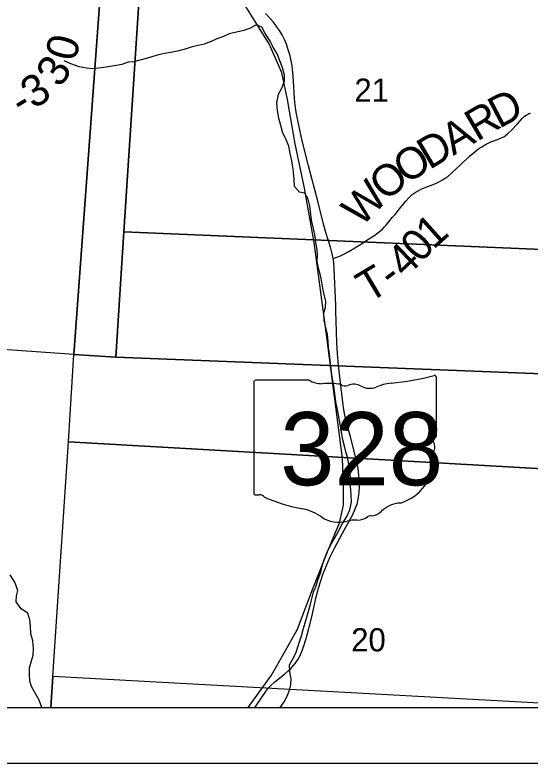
# Model space of a CAD drawing. Extents: x 0 to 34, y 0 to 22.
# Drawn here: x 5.134 to 6.063, y 14 to 15.349 of the extents above; entities that cross this region are included whole.
import ezdxf

# ---------------------------------------------------------------- set-up
doc = ezdxf.new("R2010")
doc.units = 0
for name, color, linetype in [('GM_X_Corporation', 7, 'Continuous'), ('GM_X_Minor_River', 7, 'Continuous'), ('GM_X_Rail_Line', 7, 'Continuous'), ('GM_X_Section_Text', 7, 'Continuous'), ('GM_X_State_Location', 7, 'Continuous'), ('GM_X_State_Route', 7, 'Continuous'), ('GM_X_State_Shield', 7, 'Continuous'), ('GM_X_Township_Road', 7, 'Continuous'), ('GM_X_Township_Road_Text', 7, 'Continuous'), ('SH_Data', 7, 'Continuous')]:
    doc.layers.add(name, color=color, linetype=linetype)

msp = doc.modelspace()

# ---------------------------------------------------------------- linework, layer by layer
at = {"layer": 'GM_X_Corporation'}
for points in [[(5.3151, 15.7607), (5.2401, 14.7366), (4.7622, 14.7706), (4.8134, 15.7898)], [(5.3826, 15.7568), (5.3302, 14.958), (5.3154, 14.7318), (5.2401, 14.7366), (5.3151, 15.7607)], [(6.3225, 15.705), (6.2563, 14.9189), (5.3302, 14.958), (5.3826, 15.7568)], [(6.2563, 14.9189), (6.2382, 14.6961), (5.3154, 14.7318), (5.3302, 14.958)], [(4.1967, 14.1), (5.1981, 14.1), (5.2017, 14.1562), (5.23, 14.5792), (5.2401, 14.7366), (4.7622, 14.7706), (4.245, 14.8084)], [(5.3154, 14.7318), (6.2382, 14.6961), (6.2242, 14.5225), (5.23, 14.5792), (5.2401, 14.7366)], [(5.23, 14.5792), (6.2242, 14.5225), (6.1902, 14.1019), (5.2017, 14.1562)], [(5.1981, 14.1), (6.19, 14.1), (6.1902, 14.1019), (5.2017, 14.1562)]]:
    msp.add_lwpolyline(points, close=True, dxfattribs=at)
at = {"layer": 'GM_X_Minor_River'}
for points in [[(5.667, 14.9948), (5.6657, 15.0046), (5.663, 15.0167), (5.6565, 15.0276), (5.647, 15.0294), (5.6378, 15.04), (5.6377, 15.0525), (5.6364, 15.0653), (5.6348, 15.0752), (5.6325, 15.0892), (5.6305, 15.099), (5.6277, 15.1126), (5.6223, 15.1259), (5.6173, 15.1357), (5.6134, 15.15), (5.6099, 15.1629), (5.6071, 15.1765), (5.6059, 15.1901), (5.6091, 15.2064), (5.6147, 15.216), (5.6203, 15.2297), (5.6202, 15.2407), (5.6163, 15.2535), (5.6124, 15.2652), (5.607, 15.2792), (5.5989, 15.292), (5.5939, 15.3018), (5.5851, 15.3154), (5.5789, 15.3271), (5.5694, 15.3311), (5.557, 15.3246), (5.5464, 15.3211), (5.5336, 15.3179), (5.52, 15.3152), (5.5098, 15.3105), (5.5, 15.3066), (5.4857, 15.3004), (5.4752, 15.2962), (5.4532, 15.2914), (5.4423, 15.2879), (5.4272, 15.2836), (5.4076, 15.2804), (5.3951, 15.278), (5.3826, 15.2741), (5.3728, 15.2714), (5.3589, 15.2675), (5.3479, 15.2647), (5.3381, 15.2642), (5.3264, 15.26), (5.3128, 15.2572), (5.2981, 15.2552), (5.2845, 15.2531), (5.2742, 15.2519), (5.2625, 15.2529), (5.2492, 15.2555), (5.2344, 15.261), (5.2223, 15.2666)], [(5.6123, 14.1), (5.6194, 14.1106), (5.625, 14.1205), (5.6291, 14.1312), (5.6316, 14.1414), (5.6319, 14.1516), (5.6295, 14.1645), (5.629, 14.1774), (5.6365, 14.1896), (5.6413, 14.1999), (5.6454, 14.2132), (5.6509, 14.2295), (5.6538, 14.2409), (5.6571, 14.2531), (5.6601, 14.2629), (5.6638, 14.2759), (5.6674, 14.2891), (5.67, 14.2986), (5.6725, 14.3085), (5.6763, 14.318), (5.681, 14.3317), (5.6855, 14.3443), (5.6884, 14.3572), (5.6917, 14.3667), (5.6973, 14.38), (5.7032, 14.3929), (5.7107, 14.4063), (5.7181, 14.4192), (5.7248, 14.4322), (5.7327, 14.4447), (5.7382, 14.4569), (5.7408, 14.4706), (5.7403, 14.4846), (5.7394, 14.4986), (5.7389, 14.5107), (5.7388, 14.5244), (5.7368, 14.5372), (5.7336, 14.5509), (5.7309, 14.5614), (5.7285, 14.5713), (5.725, 14.5853), (5.723, 14.5974), (5.7202, 14.6114), (5.7179, 14.6242), (5.7155, 14.6367), (5.7127, 14.6511), (5.7107, 14.6662), (5.709, 14.6802), (5.7067, 14.6923), (5.705, 14.7052), (5.7038, 14.7162), (5.7022, 14.726), (5.701, 14.7381), (5.6997, 14.7491), (5.6989, 14.7601), (5.6976, 14.773), (5.6949, 14.7855), (5.6917, 14.7976), (5.6909, 14.8116), (5.6942, 14.8218), (5.6948, 14.8328), (5.6925, 14.8427), (5.6901, 14.8525), (5.6874, 14.8672), (5.6854, 14.8771), (5.6815, 14.8922), (5.6791, 14.9047), (5.6797, 14.9157), (5.6789, 14.9259), (5.6765, 14.9384), (5.6753, 14.9497), (5.6721, 14.9641), (5.669, 14.9789), (5.667, 14.9948)], [(5.1822, 14.1), (5.1821, 14.1002), (5.1775, 14.1134), (5.1694, 14.127), (5.1632, 14.1379), (5.1605, 14.1477), (5.1596, 14.161), (5.1599, 14.1716), (5.1636, 14.1845), (5.1662, 14.1944), (5.1672, 14.2058), (5.1656, 14.2202), (5.162, 14.233), (5.1619, 14.247), (5.1603, 14.258), (5.1568, 14.2701), (5.145, 14.2783), (5.1358, 14.2908), (5.1361, 14.3018), (5.139, 14.3113), (5.1336, 14.326), (5.1252, 14.3395)]]:
    msp.add_lwpolyline(points, dxfattribs=at)
at = {"layer": 'GM_X_Rail_Line'}
msp.add_lwpolyline([(5.5547, 14.1), (5.5967, 14.1582), (5.6212, 14.2017), (5.6432, 14.2417), (5.6703, 14.3127), (5.6986, 14.3836), (5.7193, 14.433), (5.7265, 14.4652), (5.7264, 14.5008), (5.7246, 14.5493), (5.6967, 14.7678), (5.6733, 14.9386), (5.6564, 15.0367), (5.639, 15.1164), (5.6254, 15.1965), (5.6154, 15.2447), (5.593, 15.2957), (5.5443, 15.3738)], dxfattribs=at)
at = {"layer": 'GM_X_State_Route'}
msp.add_lwpolyline([(5.5667, 14.1), (5.5685, 14.1026), (5.5875, 14.131), (5.5914, 14.1359), (5.5957, 14.1405), (5.6028, 14.1466), (5.6198, 14.1602), (5.6268, 14.1662), (5.6313, 14.1705), (5.6354, 14.175), (5.6393, 14.1798), (5.6444, 14.1874), (5.6475, 14.1928), (5.6513, 14.2012), (5.6545, 14.2098), (5.6592, 14.2246), (5.6641, 14.2426), (5.6692, 14.2636), (5.6773, 14.3), (5.6812, 14.3151), (5.6849, 14.327), (5.69, 14.3417), (5.6957, 14.3562), (5.702, 14.3704), (5.7101, 14.3872), (5.7246, 14.4147), (5.7425, 14.4473), (5.7466, 14.4556), (5.749, 14.4613), (5.7509, 14.4671), (5.7525, 14.4731), (5.7537, 14.4791), (5.7549, 14.4882), (5.7553, 14.4974), (5.7551, 14.5067), (5.7542, 14.519), (5.7528, 14.5313), (5.7511, 14.5405), (5.7477, 14.5555), (5.7389, 14.5885), (5.7324, 14.6125), (5.7296, 14.6246), (5.7274, 14.6369), (5.7248, 14.6554), (5.7177, 14.7171), (5.7157, 14.7387), (5.7144, 14.7573), (5.7136, 14.7791), (5.7127, 14.8142), (5.7124, 14.8256), (5.7097, 14.8908), (5.7088, 14.9031), (5.7079, 14.9096), (5.706, 14.9182), (5.7028, 14.9301), (5.6946, 14.9568), (5.6906, 14.9718), (5.6807, 15.011), (5.6634, 15.0771), (5.6522, 15.1223), (5.644, 15.1586), (5.641, 15.1739), (5.6392, 15.1863), (5.638, 15.1987), (5.6365, 15.2297), (5.6352, 15.2451), (5.6336, 15.2574), (5.6321, 15.2666), (5.63, 15.2756), (5.6275, 15.2845), (5.6235, 15.2962), (5.62, 15.3048), (5.6158, 15.313), (5.611, 15.3209), (5.6057, 15.3285), (5.6, 15.3358), (5.594, 15.3428), (5.5855, 15.3518)], dxfattribs=at)
at = {"layer": 'GM_X_State_Shield'}
for p, q in [((5.8942, 14.5907), (5.8942, 14.6954)), ((5.5646, 14.687), (5.5646, 14.4869)), ((5.6643, 14.6905), (5.5678, 14.6905)), ((5.8941, 14.5908), (5.8942, 14.5907))]:
    msp.add_line(p, q, dxfattribs=at)
for centre, major_axis, start_param, end_param in [((5.7768, 14.9633), (0.3495, 0), 4.814394, 5.042369), ((5.8905, 14.6959), (0.00367, 0), 6.141152, 7.989035), ((5.5684, 14.6874), (0.00382, 0), 1.712693, 3.28349), ((5.6873, 14.7137), (0.037, 0), 4.042523, 4.731795), ((5.6996, 14.5781), (0.133, 0), 1.404758, 1.657858), ((5.7298, 14.6885), (0.0107, 0), 3.836095, 5.185415), ((5.7455, 14.6653), (0.0222, 0), 0.950623, 2.079405), ((5.7741, 14.6971), (0.0267, 0), 4.081561, 5.145723), ((5.8213, 14.6293), (0.0703, 0), 1.699011, 2.107814), ((5.8933, 14.583), (0.00568, 0), 1.883978, 3.671073), ((5.8902, 14.5903), (0.00393, 0), 5.05454, 6.418171), ((5.8572, 14.5698), (0.0341, 0), 5.934695, 6.695948), ((5.9073, 14.5469), (0.0248, 0), 2.387724, 3.262537), ((5.7963, 14.5336), (0.0874, 0), 5.101752, 6.440018), ((5.5684, 14.4865), (0.00385, 0), 3.00124, 4.508301), ((5.569, 14.5069), (0.0294, 0), 4.665946, 4.897461), ((5.575, 14.4753), (0.0106, 0), 0.519207, 1.627899), ((5.7088, 14.6551), (0.2524, 0), 4.195997, 4.488961), ((5.8332, 14.4307), (0.0479, 0), 1.647645, 2.488434), ((5.6336, 14.397), (0.079, 0), 0.823519, 1.323587), ((5.7725, 14.4675), (0.0282, 0), 4.937069, 5.64225), ((5.719, 14.4744), (0.0501, 0), 4.026481, 4.996735), ((5.7479, 14.4052), (0.0412, 0), 1.495662, 1.94098), ((5.7516, 14.4594), (0.0267, 0), 4.691044, 5.507374), ((5.7757, 14.44), (0.00752, 0), 1.147584, 2.315152)]:
    msp.add_ellipse(centre, major_axis=major_axis, ratio=0.8, start_param=start_param, end_param=end_param, dxfattribs=at)
at = {"layer": 'GM_X_Township_Road'}
msp.add_lwpolyline([(5.7079, 14.9096), (5.7208, 14.9148), (5.7361, 14.9224), (5.7638, 14.9394), (5.7688, 14.943), (5.7831, 14.9519), (5.789, 14.9565), (5.7963, 14.9621), (5.8007, 14.9667), (5.8036, 14.9697), (5.8144, 14.984), (5.8195, 14.9894), (5.8278, 14.9994), (5.839, 15.0132), (5.8453, 15.0199), (5.8505, 15.025), (5.8578, 15.03), (5.869, 15.036), (5.8881, 15.0433), (5.8966, 15.0472), (5.9049, 15.0516), (5.9101, 15.0548), (5.9152, 15.0585), (5.9223, 15.0645), (5.9382, 15.0794), (5.9541, 15.0942), (5.9634, 15.1025), (5.9709, 15.1081), (5.9761, 15.1115), (5.9842, 15.1161), (5.9927, 15.12), (6.0043, 15.1246), (6.0101, 15.1268), (6.0129, 15.1281), (6.0157, 15.1295), (6.0183, 15.1312), (6.0232, 15.135), (6.0299, 15.1415), (6.0404, 15.153), (6.0488, 15.1621), (6.0534, 15.1663), (6.0559, 15.1681), (6.0586, 15.1698), (6.0613, 15.1712), (6.0642, 15.1722)], dxfattribs=at)
at = {"layer": 'SH_Data'}
for p, q in [((2.1, 14.1), (8.9, 14.1)), ((2, 14), (9, 14))]:
    msp.add_line(p, q, dxfattribs=at)

# ---------------------------------------------------------------- texts
at = {"layer": 'GM_X_Section_Text'}
for s, p in [('21', (5.7463, 15.1925)), ('20', (5.7405, 14.2013))]:
    msp.add_text(s, height=0.04186, rotation=0, dxfattribs=at).set_placement(p)
at = {"layer": 'GM_X_State_Location'}
for s in ['s', 'r']:
    msp.add_text(s, height=0.000189, dxfattribs=at).set_placement((5.7257, 14.5737))
msp.add_text('328', height=0.000189, rotation=0, dxfattribs=at).set_placement((5.6588, 14.5599))
at = {"layer": 'GM_X_State_Shield'}
msp.add_text('328', height=0.13184, dxfattribs=at).set_placement((5.6122, 14.501))
at = {"layer": 'GM_X_Township_Road_Text'}
for s, rotation, p in [('0', 75.5096, (5.2421, 15.2634)), ('3', 57.56, (5.2157, 15.2161)), ('3', 32.8614, (5.1676, 15.1783)), ('D', 27.624, (6.0071, 15.1435)), ('-', 30.6944, (5.1455, 15.1652)), ('R', 30.4711, (5.9675, 15.1202)), ('A', 30.6414, (5.9245, 15.0947)), ('D', 30.6639, (5.8815, 15.0692)), ('O', 32.2077, (5.8396, 15.0428)), ('O', 41.0454, (5.8037, 15.0113)), ('W', 45.6065, (5.7585, 14.9651)), ('1', 41.9369, (5.8886, 14.9248)), ('0', 47.2529, (5.8658, 14.9001)), ('4', 44.0571, (5.8383, 14.8732)), ('T', 30.9197, (5.772, 14.8287)), ('-', 37.2313, (5.8141, 14.8543))]:
    msp.add_text(s, height=0.0568, rotation=rotation, dxfattribs=at).set_placement(p)

doc.saveas('drawing.dxf')
